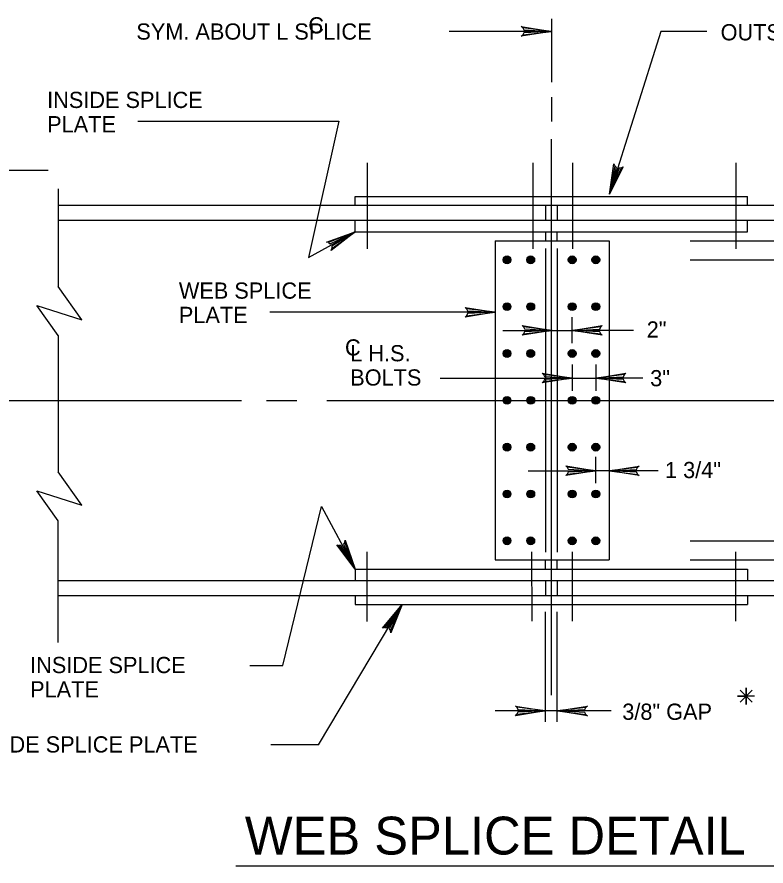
# Model space of a CAD drawing. Extents: x 638466 to 639375, y 297808 to 298996.
# Drawn here: x 638599.8 to 638749.4, y 298104.7 to 298274.3 of the extents above; entities that cross this region are included whole.
import ezdxf

# ---------------------------------------------------------------- set-up
doc = ezdxf.new("R2010")
doc.units = 0
for name, color, linetype in [('1', 7, 'Continuous'), ('2', 7, 'Continuous'), ('4', 7, 'Continuous')]:
    doc.layers.add(name, color=color, linetype=linetype)

msp = doc.modelspace()

# ---------------------------------------------------------------- linework, layer by layer
at = {"layer": '1'}
for points in [[(638700.8, 298272.15), (638701.01, 298271.73), (638706.52, 298271.43), (638700.8, 298272.15), (638700.5, 298272.4), (638706.52, 298271.43), (638701.01, 298271.16), (638700.81, 298270.75), (638706.52, 298271.43), (638700.5, 298270.48), (638700.81, 298270.75)], [(638720.5, 298244.16), (638720.04, 298244.08), (638718.09, 298238.92), (638720.5, 298244.16), (638720.83, 298244.36), (638718.09, 298238.92), (638719.49, 298244.25), (638719.16, 298244.56), (638718.09, 298238.92), (638718.99, 298244.94), (638719.16, 298244.56)], [(638661.98, 298229.26), (638662.36, 298229), (638667.34, 298231.38), (638661.98, 298229.26), (638661.6, 298229.33), (638667.34, 298231.38), (638662.65, 298228.49), (638662.67, 298228.04), (638667.34, 298231.38), (638662.53, 298227.65), (638662.67, 298228.04)], [(638689.57, 298216.02), (638689.78, 298215.61), (638695.29, 298215.3), (638689.57, 298216.02), (638689.28, 298216.27), (638695.29, 298215.3), (638689.79, 298215.03), (638689.59, 298214.62), (638695.29, 298215.3), (638689.28, 298214.35), (638689.59, 298214.62)], [(638700.93, 298212.41), (638701.14, 298212), (638706.65, 298211.69), (638700.93, 298212.41), (638700.64, 298212.66), (638706.65, 298211.69), (638701.15, 298211.42), (638700.95, 298211.01), (638706.65, 298211.69), (638700.64, 298210.74), (638700.95, 298211.01)], [(638716.37, 298210.98), (638716.16, 298211.39), (638710.65, 298211.69), (638716.37, 298210.98), (638716.66, 298210.72), (638710.65, 298211.69), (638716.15, 298211.96), (638716.35, 298212.37), (638710.65, 298211.69), (638716.66, 298212.65), (638716.35, 298212.37)], [(638704.93, 298202.89), (638705.14, 298202.47), (638710.65, 298202.17), (638704.93, 298202.89), (638704.64, 298203.14), (638710.65, 298202.17), (638705.14, 298201.9), (638704.94, 298201.48), (638710.65, 298202.17), (638704.64, 298201.21), (638704.94, 298201.48)], [(638721.09, 298201.45), (638720.88, 298201.86), (638715.37, 298202.17), (638721.09, 298201.45), (638721.39, 298201.2), (638715.37, 298202.17), (638720.88, 298202.44), (638721.08, 298202.85), (638715.37, 298202.17), (638721.39, 298203.12), (638721.08, 298202.85)], [(638709.65, 298184.35), (638709.86, 298183.94), (638715.37, 298183.64), (638709.65, 298184.35), (638709.36, 298184.61), (638715.37, 298183.64), (638709.87, 298183.37), (638709.67, 298182.95), (638715.37, 298183.64), (638709.36, 298182.68), (638709.67, 298182.95)], [(638723.74, 298182.92), (638723.52, 298183.33), (638718.02, 298183.64), (638723.74, 298182.92), (638724.03, 298182.67), (638718.02, 298183.64), (638723.52, 298183.91), (638723.72, 298184.32), (638718.02, 298183.64), (638724.03, 298184.59), (638723.72, 298184.32)], [(638665.26, 298169.37), (638664.99, 298168.99), (638667.34, 298164), (638665.26, 298169.37), (638665.34, 298169.75), (638667.34, 298164), (638664.49, 298168.71), (638664.03, 298168.69), (638667.34, 298164), (638663.65, 298168.84), (638664.03, 298168.69)], [(638673.18, 298152.35), (638673.65, 298152.32), (638676.71, 298156.91), (638673.18, 298152.35), (638672.82, 298152.22), (638676.71, 298156.91), (638674.14, 298152.03), (638674.4, 298151.65), (638676.71, 298156.91), (638674.47, 298151.24), (638674.4, 298151.65)], [(638699.61, 298136.38), (638699.82, 298135.96), (638705.33, 298135.66), (638699.61, 298136.38), (638699.32, 298136.63), (638705.33, 298135.66), (638699.83, 298135.39), (638699.63, 298134.98), (638705.33, 298135.66), (638699.32, 298134.71), (638699.63, 298134.98)], [(638713.41, 298134.94), (638713.2, 298135.36), (638707.69, 298135.66), (638713.41, 298134.94), (638713.71, 298134.69), (638707.69, 298135.66), (638713.2, 298135.93), (638713.4, 298136.34), (638707.69, 298135.66), (638713.71, 298136.62), (638713.4, 298136.34)]]:
    msp.add_lwpolyline(points, dxfattribs=at)
at = {"layer": '2'}
for p, q in [((638706.51, 298273.91), (638706.52, 298261.3)), ((638706.53, 298258.31), (638706.53, 298253.4)), ((638706.51, 298138.82), (638706.51, 298249.86)), ((638608.05, 298240), (638608.05, 298220.45)), ((638667.34, 298236.7), (638667.34, 298238.47)), ((638667.34, 298238.47), (638745.69, 298238.47)), ((638745.69, 298236.7), (638745.69, 298238.47)), ((638608.05, 298236.69), (638804.98, 298236.69)), ((638705.33, 298236.69), (638705.33, 298233.74)), ((638707.69, 298236.69), (638707.69, 298233.74)), ((638608.05, 298233.74), (638804.98, 298233.74)), ((638667.34, 298231.38), (638667.34, 298233.74)), ((638745.69, 298231.38), (638745.69, 298233.74)), ((638667.34, 298231.38), (638745.69, 298231.38)), ((638705.33, 298231.38), (638705.33, 298229.6)), ((638707.69, 298229.6), (638707.69, 298231.38)), ((638695.29, 298229.6), (638718.02, 298229.6)), ((638695.29, 298229.6), (638695.29, 298165.82)), ((638718.02, 298229.6), (638718.02, 298165.82)), ((638705.33, 298228.06), (638705.33, 298167.37)), ((638707.69, 298228.06), (638707.69, 298167.37)), ((638612.78, 298213.81), (638608.05, 298220.45)), ((638608.05, 298210.66), (638603.79, 298216.66)), ((638603.79, 298216.66), (638612.78, 298213.81)), ((638608.05, 298210.66), (638608.05, 298183.4)), ((638612.78, 298176.76), (638608.05, 298183.4)), ((638608.05, 298173.62), (638603.79, 298179.61)), ((638603.79, 298179.61), (638612.78, 298176.76)), ((638608.05, 298149.31), (638608.05, 298173.62)), ((638695.29, 298165.82), (638718.02, 298165.82)), ((638705.33, 298164), (638705.33, 298165.82)), ((638707.69, 298164), (638707.69, 298165.82)), ((638667.34, 298164), (638745.69, 298164)), ((638667.34, 298164), (638667.34, 298161.63)), ((638745.69, 298164), (638745.69, 298161.63)), ((638608.05, 298161.69), (638804.98, 298161.69)), ((638705.33, 298161.63), (638705.33, 298158.73)), ((638707.69, 298161.63), (638707.69, 298158.73)), ((638608.05, 298158.73), (638804.98, 298158.73)), ((638667.34, 298158.68), (638667.34, 298156.91)), ((638745.69, 298158.68), (638745.69, 298156.91)), ((638667.34, 298156.91), (638745.69, 298156.91))]:
    msp.add_line(p, q, dxfattribs=at)
for centre, radius in [((638697.65, 298225.78), 0.783), ((638697.65, 298225.78), 0.727), ((638697.65, 298225.78), 0.672), ((638697.65, 298225.78), 0.616), ((638697.65, 298225.78), 0.561), ((638697.65, 298225.78), 0.505), ((638697.65, 298225.78), 0.449), ((638697.65, 298225.78), 0.394), ((638697.65, 298225.78), 0.338), ((638697.65, 298225.78), 0.283), ((638697.65, 298225.78), 0.227), ((638697.65, 298225.78), 0.171), ((638697.65, 298225.78), 0.116), ((638697.65, 298225.78), 0.0601), ((638702.38, 298225.78), 0.783), ((638702.38, 298225.78), 0.727), ((638702.38, 298225.78), 0.672), ((638702.38, 298225.78), 0.616), ((638702.38, 298225.78), 0.561), ((638702.38, 298225.78), 0.505), ((638702.38, 298225.78), 0.449), ((638702.38, 298225.78), 0.394), ((638702.38, 298225.78), 0.338), ((638702.38, 298225.78), 0.283), ((638702.38, 298225.78), 0.227), ((638702.38, 298225.78), 0.171), ((638702.38, 298225.78), 0.116), ((638702.38, 298225.78), 0.0601), ((638710.65, 298225.78), 0.783), ((638710.65, 298225.78), 0.727), ((638710.65, 298225.78), 0.672), ((638710.65, 298225.78), 0.616), ((638710.65, 298225.78), 0.561), ((638710.65, 298225.78), 0.505), ((638710.65, 298225.78), 0.449), ((638710.65, 298225.78), 0.394), ((638710.65, 298225.78), 0.338), ((638710.65, 298225.78), 0.283), ((638710.65, 298225.78), 0.227), ((638710.65, 298225.78), 0.171), ((638710.65, 298225.78), 0.116), ((638710.65, 298225.78), 0.0601), ((638715.38, 298225.78), 0.783), ((638715.38, 298225.78), 0.727), ((638715.38, 298225.78), 0.672), ((638715.38, 298225.78), 0.616), ((638715.38, 298225.78), 0.561), ((638715.38, 298225.78), 0.505), ((638715.38, 298225.78), 0.449), ((638715.38, 298225.78), 0.394), ((638715.38, 298225.78), 0.338), ((638715.38, 298225.78), 0.283), ((638715.38, 298225.78), 0.227), ((638715.38, 298225.78), 0.171), ((638715.38, 298225.78), 0.116), ((638715.38, 298225.78), 0.0601), ((638697.65, 298216.43), 0.783), ((638697.65, 298216.43), 0.727), ((638697.65, 298216.43), 0.672), ((638697.65, 298216.43), 0.616), ((638697.65, 298216.43), 0.561), ((638697.65, 298216.43), 0.505), ((638697.65, 298216.43), 0.449), ((638697.65, 298216.43), 0.394), ((638697.65, 298216.43), 0.338), ((638697.65, 298216.43), 0.283), ((638697.65, 298216.43), 0.227), ((638697.65, 298216.43), 0.171), ((638697.65, 298216.43), 0.116), ((638697.65, 298216.43), 0.0601), ((638702.38, 298216.43), 0.783), ((638702.38, 298216.43), 0.727), ((638702.38, 298216.43), 0.672), ((638702.38, 298216.43), 0.616), ((638702.38, 298216.43), 0.561), ((638702.38, 298216.43), 0.505), ((638702.38, 298216.43), 0.449), ((638702.38, 298216.43), 0.394), ((638702.38, 298216.43), 0.338), ((638702.38, 298216.43), 0.283), ((638702.38, 298216.43), 0.227), ((638702.38, 298216.43), 0.171), ((638702.38, 298216.43), 0.116), ((638702.38, 298216.43), 0.0601), ((638710.65, 298216.43), 0.783), ((638710.65, 298216.43), 0.727), ((638710.65, 298216.43), 0.672), ((638710.65, 298216.43), 0.616), ((638710.65, 298216.43), 0.561), ((638710.65, 298216.43), 0.505), ((638710.65, 298216.43), 0.449), ((638710.65, 298216.43), 0.394), ((638710.65, 298216.43), 0.338), ((638710.65, 298216.43), 0.283), ((638710.65, 298216.43), 0.227), ((638710.65, 298216.43), 0.171), ((638710.65, 298216.43), 0.116), ((638710.65, 298216.43), 0.0601), ((638715.38, 298216.43), 0.783), ((638715.38, 298216.43), 0.727), ((638715.38, 298216.43), 0.672), ((638715.38, 298216.43), 0.616), ((638715.38, 298216.43), 0.561), ((638715.38, 298216.43), 0.505), ((638715.38, 298216.43), 0.449), ((638715.38, 298216.43), 0.394), ((638715.38, 298216.43), 0.338), ((638715.38, 298216.43), 0.283), ((638715.38, 298216.43), 0.227), ((638715.38, 298216.43), 0.171), ((638715.38, 298216.43), 0.116), ((638715.38, 298216.43), 0.0601), ((638697.65, 298207.07), 0.783), ((638697.65, 298207.07), 0.727), ((638697.65, 298207.07), 0.672), ((638697.65, 298207.07), 0.616), ((638697.65, 298207.07), 0.561), ((638697.65, 298207.07), 0.505), ((638697.65, 298207.07), 0.449), ((638697.65, 298207.07), 0.394), ((638697.65, 298207.07), 0.338), ((638697.65, 298207.07), 0.283), ((638697.65, 298207.07), 0.227), ((638697.65, 298207.07), 0.171), ((638697.65, 298207.07), 0.116), ((638697.65, 298207.07), 0.0601), ((638702.38, 298207.07), 0.783), ((638702.38, 298207.07), 0.727), ((638702.38, 298207.07), 0.672), ((638702.38, 298207.07), 0.616), ((638702.38, 298207.07), 0.561), ((638702.38, 298207.07), 0.505), ((638702.38, 298207.07), 0.449), ((638702.38, 298207.07), 0.394), ((638702.38, 298207.07), 0.338), ((638702.38, 298207.07), 0.283), ((638702.38, 298207.07), 0.227), ((638702.38, 298207.07), 0.171), ((638702.38, 298207.07), 0.116), ((638702.38, 298207.07), 0.0601), ((638710.65, 298207.07), 0.783), ((638710.65, 298207.07), 0.727), ((638710.65, 298207.07), 0.672), ((638710.65, 298207.07), 0.616), ((638710.65, 298207.07), 0.561), ((638710.65, 298207.07), 0.505), ((638710.65, 298207.07), 0.449), ((638710.65, 298207.07), 0.394), ((638710.65, 298207.07), 0.338), ((638710.65, 298207.07), 0.283), ((638710.65, 298207.07), 0.227), ((638710.65, 298207.07), 0.171), ((638710.65, 298207.07), 0.116), ((638710.65, 298207.07), 0.0601), ((638715.38, 298207.07), 0.783), ((638715.38, 298207.07), 0.727), ((638715.38, 298207.07), 0.672), ((638715.38, 298207.07), 0.616), ((638715.38, 298207.07), 0.561), ((638715.38, 298207.07), 0.505), ((638715.38, 298207.07), 0.449), ((638715.38, 298207.07), 0.394), ((638715.38, 298207.07), 0.338), ((638715.38, 298207.07), 0.283), ((638715.38, 298207.07), 0.227), ((638715.38, 298207.07), 0.171), ((638715.38, 298207.07), 0.116), ((638715.38, 298207.07), 0.0601), ((638697.65, 298197.72), 0.783), ((638697.65, 298197.72), 0.727), ((638697.65, 298197.72), 0.672), ((638697.65, 298197.72), 0.616), ((638697.65, 298197.72), 0.561), ((638697.65, 298197.72), 0.505), ((638697.65, 298197.72), 0.449), ((638697.65, 298197.72), 0.394), ((638697.65, 298197.72), 0.338), ((638697.65, 298197.72), 0.283), ((638697.65, 298197.72), 0.227), ((638697.65, 298197.72), 0.171), ((638697.65, 298197.72), 0.116), ((638697.65, 298197.72), 0.0601), ((638702.38, 298197.72), 0.783), ((638702.38, 298197.72), 0.727), ((638702.38, 298197.72), 0.672), ((638702.38, 298197.72), 0.616), ((638702.38, 298197.72), 0.561), ((638702.38, 298197.72), 0.505), ((638702.38, 298197.72), 0.449), ((638702.38, 298197.72), 0.394), ((638702.38, 298197.72), 0.338), ((638702.38, 298197.72), 0.283), ((638702.38, 298197.72), 0.227), ((638702.38, 298197.72), 0.171), ((638702.38, 298197.72), 0.116), ((638702.38, 298197.72), 0.0601), ((638710.65, 298197.72), 0.783), ((638710.65, 298197.72), 0.727), ((638710.65, 298197.72), 0.672), ((638710.65, 298197.72), 0.616), ((638710.65, 298197.72), 0.561), ((638710.65, 298197.72), 0.505), ((638710.65, 298197.72), 0.449), ((638710.65, 298197.72), 0.394), ((638710.65, 298197.72), 0.338), ((638710.65, 298197.72), 0.283), ((638710.65, 298197.72), 0.227), ((638710.65, 298197.72), 0.171), ((638710.65, 298197.72), 0.116), ((638710.65, 298197.72), 0.0601), ((638715.38, 298197.72), 0.783), ((638715.38, 298197.72), 0.727), ((638715.38, 298197.72), 0.672), ((638715.38, 298197.72), 0.616), ((638715.38, 298197.72), 0.561), ((638715.38, 298197.72), 0.505), ((638715.38, 298197.72), 0.449), ((638715.38, 298197.72), 0.394), ((638715.38, 298197.72), 0.338), ((638715.38, 298197.72), 0.283), ((638715.38, 298197.72), 0.227), ((638715.38, 298197.72), 0.171), ((638715.38, 298197.72), 0.116), ((638715.38, 298197.72), 0.0601), ((638697.65, 298188.36), 0.783), ((638697.65, 298188.36), 0.727), ((638697.65, 298188.36), 0.672), ((638697.65, 298188.36), 0.616), ((638697.65, 298188.36), 0.561), ((638697.65, 298188.36), 0.505), ((638697.65, 298188.36), 0.449), ((638697.65, 298188.36), 0.394), ((638697.65, 298188.36), 0.338), ((638697.65, 298188.36), 0.283), ((638697.65, 298188.36), 0.227), ((638697.65, 298188.36), 0.171), ((638697.65, 298188.36), 0.116), ((638697.65, 298188.36), 0.0601), ((638702.38, 298188.36), 0.783), ((638702.38, 298188.36), 0.727), ((638702.38, 298188.36), 0.672), ((638702.38, 298188.36), 0.616), ((638702.38, 298188.36), 0.561), ((638702.38, 298188.36), 0.505), ((638702.38, 298188.36), 0.449), ((638702.38, 298188.36), 0.394), ((638702.38, 298188.36), 0.338), ((638702.38, 298188.36), 0.283), ((638702.38, 298188.36), 0.227), ((638702.38, 298188.36), 0.171), ((638702.38, 298188.36), 0.116), ((638702.38, 298188.36), 0.0601), ((638710.65, 298188.36), 0.783), ((638710.65, 298188.36), 0.727), ((638710.65, 298188.36), 0.672), ((638710.65, 298188.36), 0.616), ((638710.65, 298188.36), 0.561), ((638710.65, 298188.36), 0.505), ((638710.65, 298188.36), 0.449), ((638710.65, 298188.36), 0.394), ((638710.65, 298188.36), 0.338), ((638710.65, 298188.36), 0.283), ((638710.65, 298188.36), 0.227), ((638710.65, 298188.36), 0.171), ((638710.65, 298188.36), 0.116), ((638710.65, 298188.36), 0.0601), ((638715.38, 298188.36), 0.783), ((638715.38, 298188.36), 0.727), ((638715.38, 298188.36), 0.672), ((638715.38, 298188.36), 0.616), ((638715.38, 298188.36), 0.561), ((638715.38, 298188.36), 0.505), ((638715.38, 298188.36), 0.449), ((638715.38, 298188.36), 0.394), ((638715.38, 298188.36), 0.338), ((638715.38, 298188.36), 0.283), ((638715.38, 298188.36), 0.227), ((638715.38, 298188.36), 0.171), ((638715.38, 298188.36), 0.116), ((638715.38, 298188.36), 0.0601), ((638697.65, 298179), 0.783), ((638697.65, 298179), 0.727), ((638697.65, 298179), 0.672), ((638697.65, 298179), 0.616), ((638697.65, 298179), 0.561), ((638697.65, 298179), 0.505), ((638697.65, 298179), 0.449), ((638697.65, 298179), 0.394), ((638697.65, 298179), 0.338), ((638697.65, 298179), 0.283), ((638697.65, 298179), 0.227), ((638697.65, 298179), 0.171), ((638697.65, 298179), 0.116), ((638697.65, 298179), 0.0601), ((638702.38, 298179), 0.783), ((638702.38, 298179), 0.727), ((638702.38, 298179), 0.672), ((638702.38, 298179), 0.616), ((638702.38, 298179), 0.561), ((638702.38, 298179), 0.505), ((638702.38, 298179), 0.449), ((638702.38, 298179), 0.394), ((638702.38, 298179), 0.338), ((638702.38, 298179), 0.283), ((638702.38, 298179), 0.227), ((638702.38, 298179), 0.171), ((638702.38, 298179), 0.116), ((638702.38, 298179), 0.0601), ((638710.65, 298179), 0.783), ((638710.65, 298179), 0.727), ((638710.65, 298179), 0.672), ((638710.65, 298179), 0.616), ((638710.65, 298179), 0.561), ((638710.65, 298179), 0.505), ((638710.65, 298179), 0.449), ((638710.65, 298179), 0.394), ((638710.65, 298179), 0.338), ((638710.65, 298179), 0.283), ((638710.65, 298179), 0.227), ((638710.65, 298179), 0.171), ((638710.65, 298179), 0.116), ((638710.65, 298179), 0.0601), ((638715.38, 298179), 0.783), ((638715.38, 298179), 0.727), ((638715.38, 298179), 0.672), ((638715.38, 298179), 0.616), ((638715.38, 298179), 0.561), ((638715.38, 298179), 0.505), ((638715.38, 298179), 0.449), ((638715.38, 298179), 0.394), ((638715.38, 298179), 0.338), ((638715.38, 298179), 0.283), ((638715.38, 298179), 0.227), ((638715.38, 298179), 0.171), ((638715.38, 298179), 0.116), ((638715.38, 298179), 0.0601), ((638697.65, 298169.65), 0.783), ((638697.65, 298169.65), 0.727), ((638697.65, 298169.65), 0.672), ((638697.65, 298169.65), 0.616), ((638697.65, 298169.65), 0.561), ((638697.65, 298169.65), 0.505), ((638697.65, 298169.65), 0.449), ((638697.65, 298169.65), 0.394), ((638697.65, 298169.65), 0.338), ((638697.65, 298169.65), 0.283), ((638697.65, 298169.65), 0.227), ((638697.65, 298169.65), 0.171), ((638697.65, 298169.65), 0.116), ((638702.38, 298169.65), 0.783), ((638702.38, 298169.65), 0.727), ((638702.38, 298169.65), 0.672), ((638702.38, 298169.65), 0.616), ((638702.38, 298169.65), 0.561), ((638702.38, 298169.65), 0.505), ((638702.38, 298169.65), 0.449), ((638702.38, 298169.65), 0.394), ((638702.38, 298169.65), 0.338), ((638702.38, 298169.65), 0.283), ((638702.38, 298169.65), 0.227), ((638702.38, 298169.65), 0.171), ((638702.38, 298169.65), 0.116), ((638710.65, 298169.65), 0.783), ((638710.65, 298169.65), 0.727), ((638710.65, 298169.65), 0.672), ((638710.65, 298169.65), 0.616), ((638710.65, 298169.65), 0.561), ((638710.65, 298169.65), 0.505), ((638710.65, 298169.65), 0.449), ((638710.65, 298169.65), 0.394), ((638710.65, 298169.65), 0.338), ((638710.65, 298169.65), 0.283), ((638710.65, 298169.65), 0.227), ((638710.65, 298169.65), 0.171), ((638710.65, 298169.65), 0.116), ((638715.38, 298169.65), 0.783), ((638715.38, 298169.65), 0.727), ((638715.38, 298169.65), 0.672), ((638715.38, 298169.65), 0.616), ((638715.38, 298169.65), 0.561), ((638715.38, 298169.65), 0.505), ((638715.38, 298169.65), 0.449), ((638715.38, 298169.65), 0.394), ((638715.38, 298169.65), 0.338), ((638715.38, 298169.65), 0.283), ((638715.38, 298169.65), 0.227), ((638715.38, 298169.65), 0.171), ((638715.38, 298169.65), 0.116), ((638697.65, 298169.65), 0.0601), ((638702.38, 298169.65), 0.0601), ((638710.65, 298169.65), 0.0601), ((638715.38, 298169.65), 0.0601)]:
    msp.add_circle(centre, radius, dxfattribs=at)
at = {"layer": '4'}
for p, q in [((638706.52, 298271.43), (638686.08, 298271.43)), ((638728.37, 298271.43), (638718.09, 298238.92)), ((638737.53, 298271.43), (638728.37, 298271.43)), ((638623.96, 298253.52), (638664.04, 298253.52)), ((638664.04, 298253.52), (638658.04, 298226.27)), ((638669.7, 298245.14), (638669.71, 298227.96)), ((638702.78, 298245.16), (638702.77, 298227.99)), ((638710.75, 298245.16), (638710.73, 298227.98)), ((638743.33, 298245.14), (638743.32, 298227.96)), ((638606.06, 298243.61), (638583.81, 298243.61)), ((638658.04, 298226.27), (638667.34, 298231.38)), ((638734.19, 298229.6), (638769.61, 298229.6)), ((638734.19, 298225.78), (638769.61, 298225.78)), ((638695.29, 298215.3), (638650.32, 298215.3)), ((638710.65, 298209.11), (638710.65, 298214.34)), ((638696.79, 298211.69), (638706.65, 298211.69)), ((638706.64, 298211.69), (638710.65, 298211.69)), ((638722.92, 298211.69), (638710.65, 298211.69)), ((638710.65, 298204.84), (638710.65, 298199.61)), ((638715.37, 298204.84), (638715.37, 298199.61)), ((638684.29, 298202.17), (638710.65, 298202.17)), ((638710.65, 298202.17), (638715.37, 298202.17)), ((638724.79, 298202.17), (638715.37, 298202.17)), ((638581.91, 298197.71), (638644.67, 298197.71)), ((638649.61, 298197.71), (638655.66, 298197.71)), ((638661.7, 298197.71), (638760.25, 298197.71)), ((638715.37, 298181.18), (638715.37, 298186.41)), ((638701.89, 298183.64), (638715.37, 298183.64)), ((638727.79, 298183.64), (638715.37, 298183.64)), ((638652.91, 298144.75), (638660.61, 298176.49)), ((638660.61, 298176.49), (638667.34, 298164)), ((638734.19, 298169.65), (638769.61, 298169.65)), ((638669.7, 298153.55), (638669.71, 298167.47)), ((638702.64, 298153.58), (638702.63, 298167.44)), ((638710.74, 298153.58), (638710.73, 298167.45)), ((638743.32, 298153.61), (638743.32, 298167.47)), ((638734.19, 298165.82), (638769.61, 298165.82)), ((638660.01, 298128.9), (638676.71, 298156.91)), ((638705.33, 298133.51), (638705.33, 298155.46)), ((638707.69, 298133.46), (638707.69, 298155.46)), ((638646.29, 298144.75), (638652.91, 298144.75)), ((638745.36, 298138.62), (638745.36, 298138.62)), ((638718.44, 298135.66), (638695.25, 298135.66)), ((638660.01, 298128.9), (638650.51, 298128.9)), ((638770.99, 298104.67), (638643.53, 298104.67))]:
    msp.add_line(p, q, dxfattribs=at)
msp.add_lwpolyline([(638747.05, 298138.62), (638743.68, 298138.62), (638745.36, 298138.62), (638745.36, 298136.93), (638745.36, 298140.3), (638745.36, 298138.62), (638746.56, 298139.81), (638744.17, 298137.42), (638745.36, 298138.62), (638746.56, 298137.42), (638744.17, 298139.81)], dxfattribs=at)

# ---------------------------------------------------------------- texts
for s, height, p in [('C', 3.24, (638657.98, 298271.02)), ('SYM. ABOUT L SPLICE', 3.2401, (638623.65, 298269.78)), ('OUTSIDE SPLICE PLATE', 3.2401, (638740.29, 298269.63)), ('INSIDE SPLICE', 3.2401, (638605.84, 298256.12)), ('PLATE', 3.24, (638605.84, 298251.26)), ('WEB SPLICE', 3.24, (638632.14, 298218.02)), ('PLATE', 3.24, (638632.14, 298213.16)), ('2"', 3.24, (638725.54, 298210.25)), ('C', 3.24, (638665.3, 298206.66)), ('L H.S.', 3.24, (638666.35, 298205.51)), ('BOLTS', 3.24, (638666.35, 298200.66)), ('3"', 3.24, (638726.23, 298200.52)), ('1 3/4"', 3.24, (638729.19, 298182.17)), ('INSIDE SPLICE', 3.2401, (638602.44, 298143.21)), ('PLATE', 3.24, (638602.44, 298138.35)), ('3/8" GAP', 3.24, (638720.66, 298133.88)), ('OUTSIDE SPLICE PLATE', 3.2401, (638585.09, 298127.35)), ('WEB SPLICE DETAIL', 7.56, (638645.31, 298106.97))]:
    msp.add_text(s, height=height, dxfattribs=at).set_placement(p)

doc.saveas('drawing.dxf')
